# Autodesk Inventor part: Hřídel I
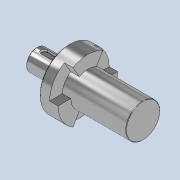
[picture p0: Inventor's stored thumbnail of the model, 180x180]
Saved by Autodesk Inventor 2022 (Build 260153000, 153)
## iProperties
Created: 2025-05
Part Number: Hřídel I
Material: Všeobecné
Document SubType Name: Modeling
Designer: jbart
Density: 1 g/cm^3
Appearance: Broušená
Mass: 1371.09 g
Surface Area: 961.388 cm^2
Volume: 1371.09 cm^3
Author: jbart
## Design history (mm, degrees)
sketch "Náčrt1"
  geometry: L1 (0, 0)-(100, 0); L2 (0, 0)-(0, 25); L3 (0, 25)-(76, 25); L4 (76, 25)-(76, 70); L5 (76, 70)-(100, 70); L6 (100, 70)-(100, 0)
  constraints: 12 end point, 4 perpendicular, 1 horizontal, 1 vertical
  dimensions: "d0" = 100 distance of L1.start L1.end; "d2" = 76 distance of L2.end L3.end; "d3" = 50 diameter of L3 L1; "d4" = 140 diameter of L5 L1
revolve "Rotace1" sketch "Náčrt1" stored, may be unused: angle "d5" = 90 deg
node "Pracovní rovina1"
sketch "Náčrt2"
  geometry: L1 (-10, 0)-(-60, 0); L2 (-18, 8)-(-52, 8); L3 (-52, -8)-(-18, -8); L4 (-76, 70)-(-76, -70) reference; A1 r 8 centre (-18, 0) between (-18, -8) and (-18, 8); A2 r 8 centre (-52, 0) between (-52, 8) and (-52, -8); 2 further points
  constraints: 8 end point, 6 point on circle, 4 tangent, 2 centre point, 2 point on line, 1 horizontal, 1 horizontal alignment, 1 midpoint, 1 parallel
  dimensions: "d7" = 50 distance of L1.start L1.end; "d8" = 16 diameter of A2; "d16" = 16 distance from line of L4 L1.end
extrude "Vysunutí1" cut sketch "Náčrt2" distance "d10" = 6.2; taper "d11" = 0 deg
fillet "Zaoblení1" dims "d12" = 0.6
chamfer "Zkosení1" distance "d13" = 1; stored, may be unused: second distance "d14" = 2, angle "d15" = 45 deg
sketch "Náčrt3"
  geometry: L1 (0, 0)-(0, 70); L2 (-20, 34.641)-(-35, 60.622); L3 (20, 34.641)-(35, 60.622); L4 (-20, 34.641)-(0, 0); L5 (20, 34.641)-(0, 0); A1 r 70 centre (0, 0) between (0, 70) and (-35, 60.622) reference; A2 r 40 centre (0, 0) between (20, 34.641) and (-20, 34.641); 1 further point
  constraints: 10 end point, 5 point on circle, 2 coincident, 1 centre point, 1 vertical
  dimensions: "d17" = 80 diameter of A2; "d18" = 60 deg angle of L2 L3; "d19" = 30 deg angle of L2 L1; "d20" = 30 deg angle of L1 L4; "d21" = 60 deg angle of L4 L5
extrude "Vysunutí2" join sketch "Náčrt3" distance "d22" = 20; taper "d23" = 0 deg
pattern_circular "Kruhové pole1" dims angle "d25" = 360 deg
chamfer "Zkosení2" distance "d27" = 2; stored, may be unused: second distance "d28" = 2, angle "d29" = 45 deg
fillet "Zaoblení2" dims "d30" = 2
sketch "Náčrt5"
  geometry: C1 r 40 at (0, 0); 1 further point
  constraints: 1 centre point, 1 coincident
  dimensions: "d32" = 80 diameter of C1
extrude "Vysunutí3" join sketch "Náčrt5" distance "d33" = 150; taper "d34" = 0 deg
chamfer "Zkosení3" distance "d35" = 1; stored, may be unused: second distance "d36" = 2, angle "d37" = 45 deg
node "Těleso1"
other parameters: "d6" = 25
